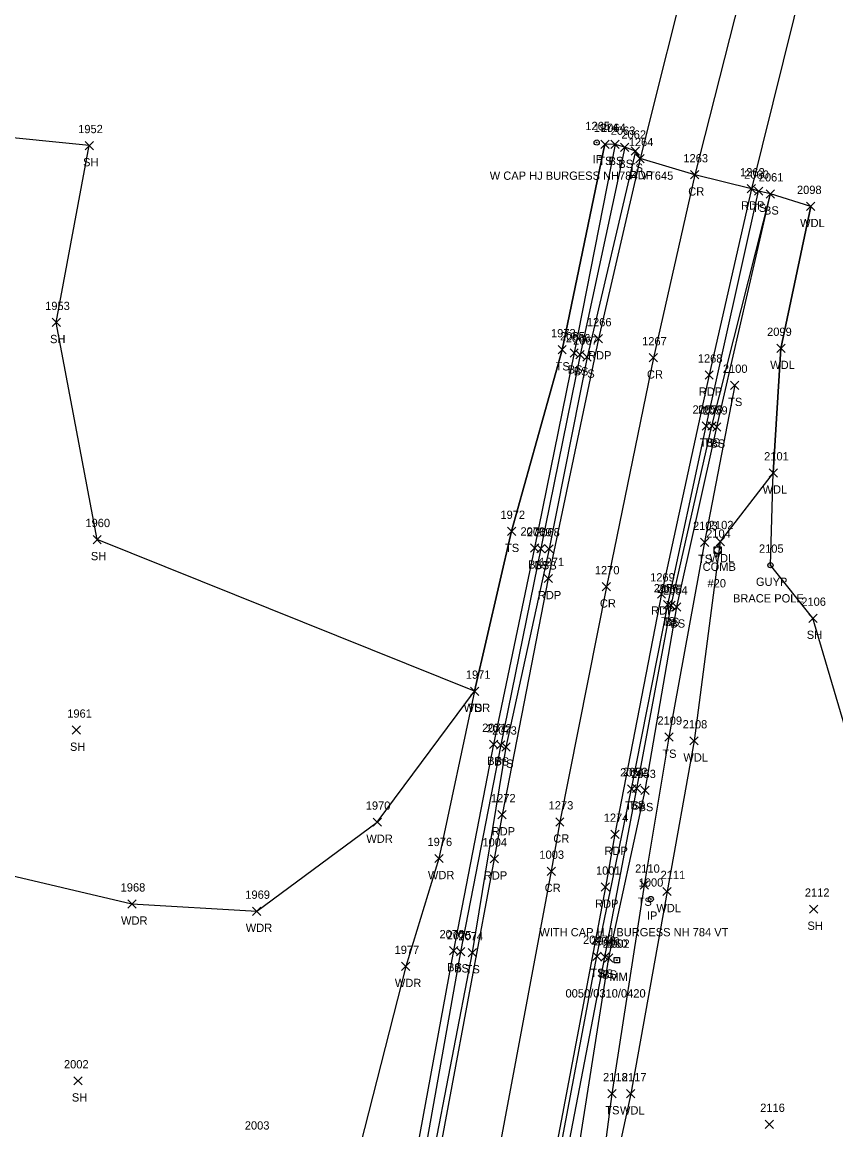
# Model space of a CAD drawing. Extents: x 1754529 to 1755810, y 621660 to 624656.
# Drawn here: x 1755421.2 to 1755617.5, y 624067.2 to 624334.6 of the extents above; entities that cross this region are included whole.
import ezdxf

# ---------------------------------------------------------------- set-up
doc = ezdxf.new("R2010")
doc.units = 0
for name, color, linetype in [('L_A', 7, 'Continuous'), ('L_I', 7, 'Continuous'), ('L_TIC', 7, 'Continuous'), ('LAWA', 7, 'Continuous'), ('LELB', 7, 'Continuous'), ('Level 14', 7, 'Continuous'), ('LSOGP', 7, 'Continuous'), ('M_A', 7, 'Continuous'), ('M_C', 7, 'Continuous'), ('M_I', 7, 'Continuous'), ('MPIR', 7, 'Continuous'), ('P_A', 7, 'Continuous'), ('P_I', 7, 'Continuous'), ('PET', 7, 'Continuous'), ('PRC', 7, 'Continuous'), ('S_A', 7, 'Continuous'), ('S_C', 7, 'Continuous'), ('S_I', 7, 'Continuous'), ('SRM', 7, 'Continuous'), ('U_A', 7, 'Continuous'), ('U_C', 7, 'Continuous'), ('U_I', 7, 'Continuous'), ('UP', 7, 'Continuous'), ('UPGW', 7, 'Continuous')]:
    doc.layers.add(name, color=color, linetype=linetype)

msp = doc.modelspace()

# ---------------------------------------------------------------- linework, layer by layer
at = {"layer": 'L_TIC'}
for points in [[(1755436.36, 624303.76), (1755438.36, 624305.76)], [(1755438.36, 624303.76), (1755436.36, 624305.76)], [(1755560.77, 624304.07), (1755562.77, 624306.07)], [(1755562.77, 624304.07), (1755560.77, 624306.07)], [(1755563.22, 624304.05), (1755565.22, 624306.05)], [(1755565.22, 624304.05), (1755563.22, 624306.05)], [(1755565.56, 624303.36), (1755567.56, 624305.36)], [(1755567.56, 624303.36), (1755565.56, 624305.36)], [(1755568.13, 624302.44), (1755570.13, 624304.44)], [(1755570.13, 624302.44), (1755568.13, 624304.44)], [(1755597.86, 624292.76), (1755599.86, 624294.76)], [(1755599.86, 624292.76), (1755597.86, 624294.76)], [(1755600.72, 624292.11), (1755602.72, 624294.11)], [(1755602.72, 624292.11), (1755600.72, 624294.11)], [(1755600.72, 624292.11), (1755602.72, 624294.11)], [(1755602.72, 624292.11), (1755600.72, 624294.11)], [(1755610.46, 624289.08), (1755612.46, 624291.08)], [(1755612.46, 624289.08), (1755610.46, 624291.08)], [(1755428.39, 624261.07), (1755430.39, 624263.07)], [(1755430.39, 624261.07), (1755428.39, 624263.07)], [(1755550.47, 624254.48), (1755552.47, 624256.48)], [(1755552.47, 624254.48), (1755550.47, 624256.48)], [(1755603.25, 624254.82), (1755605.25, 624256.82)], [(1755605.25, 624254.82), (1755603.25, 624256.82)], [(1755553.36, 624253.73), (1755555.36, 624255.73)], [(1755555.36, 624253.73), (1755553.36, 624255.73)], [(1755554.78, 624253.28), (1755556.78, 624255.28)], [(1755556.78, 624253.28), (1755554.78, 624255.28)], [(1755556.49, 624252.71), (1755558.49, 624254.71)], [(1755558.49, 624252.71), (1755556.49, 624254.71)], [(1755592.11, 624245.9), (1755594.11, 624247.9)], [(1755594.11, 624245.9), (1755592.11, 624247.9)], [(1755585.25, 624236.06), (1755587.25, 624238.06)], [(1755587.25, 624236.06), (1755585.25, 624238.06)], [(1755586.59, 624236.08), (1755588.59, 624238.08)], [(1755588.59, 624236.08), (1755586.59, 624238.08)], [(1755587.79, 624235.83), (1755589.79, 624237.83)], [(1755589.79, 624235.83), (1755587.79, 624237.83)], [(1755601.4, 624224.76), (1755603.4, 624226.76)], [(1755603.4, 624224.76), (1755601.4, 624226.76)], [(1755538.26, 624210.65), (1755540.26, 624212.65)], [(1755540.26, 624210.65), (1755538.26, 624212.65)], [(1755438.25, 624208.67), (1755440.25, 624210.67)], [(1755440.25, 624208.67), (1755438.25, 624210.67)], [(1755543.82, 624206.63), (1755545.82, 624208.63)], [(1755545.82, 624206.63), (1755543.82, 624208.63)], [(1755545.32, 624206.47), (1755547.32, 624208.47)], [(1755547.32, 624206.47), (1755545.32, 624208.47)], [(1755547.32, 624206.42), (1755549.32, 624208.42)], [(1755549.32, 624206.42), (1755547.32, 624208.42)], [(1755584.82, 624208), (1755586.82, 624210)], [(1755586.82, 624208), (1755584.82, 624210)], [(1755588.62, 624208.18), (1755590.62, 624210.18)], [(1755590.62, 624208.18), (1755588.62, 624210.18)], [(1755575.95, 624192.92), (1755577.95, 624194.92)], [(1755577.95, 624192.92), (1755575.95, 624194.92)], [(1755576.75, 624192.77), (1755578.75, 624194.77)], [(1755578.75, 624192.77), (1755576.75, 624194.77)], [(1755578.12, 624192.4), (1755580.12, 624194.4)], [(1755580.12, 624192.4), (1755578.12, 624194.4)], [(1755610.99, 624189.67), (1755612.99, 624191.67)], [(1755612.99, 624189.67), (1755610.99, 624191.67)], [(1755529.35, 624172.06), (1755531.35, 624174.06)], [(1755531.35, 624172.06), (1755529.35, 624174.06)], [(1755529.35, 624172.06), (1755531.35, 624174.06)], [(1755531.35, 624172.06), (1755529.35, 624174.06)], [(1755433.2, 624162.66), (1755435.2, 624164.66)], [(1755435.2, 624162.66), (1755433.2, 624164.66)], [(1755576.23, 624160.97), (1755578.23, 624162.97)], [(1755578.23, 624160.97), (1755576.23, 624162.97)], [(1755533.93, 624159.24), (1755535.93, 624161.24)], [(1755535.93, 624159.24), (1755533.93, 624161.24)], [(1755535.63, 624159.1), (1755537.63, 624161.1)], [(1755537.63, 624159.1), (1755535.63, 624161.1)], [(1755536.91, 624158.58), (1755538.91, 624160.58)], [(1755538.91, 624158.58), (1755536.91, 624160.58)], [(1755582.3, 624160.08), (1755584.3, 624162.08)], [(1755584.3, 624160.08), (1755582.3, 624162.08)], [(1755567.22, 624148.47), (1755569.22, 624150.47)], [(1755569.22, 624148.47), (1755567.22, 624150.47)], [(1755568.47, 624148.58), (1755570.47, 624150.58)], [(1755570.47, 624148.58), (1755568.47, 624150.58)], [(1755570.46, 624148.1), (1755572.46, 624150.1)], [(1755572.46, 624148.1), (1755570.46, 624150.1)], [(1755505.85, 624140.45), (1755507.85, 624142.45)], [(1755507.85, 624140.45), (1755505.85, 624142.45)], [(1755520.71, 624131.68), (1755522.71, 624133.68)], [(1755522.71, 624131.68), (1755520.71, 624133.68)], [(1755570.27, 624125.25), (1755572.27, 624127.25)], [(1755572.27, 624125.25), (1755570.27, 624127.25)], [(1755575.77, 624123.71), (1755577.77, 624125.71)], [(1755577.77, 624123.71), (1755575.77, 624125.71)], [(1755446.66, 624120.7), (1755448.66, 624122.7)], [(1755448.66, 624120.7), (1755446.66, 624122.7)], [(1755476.75, 624118.95), (1755478.75, 624120.95)], [(1755478.75, 624118.95), (1755476.75, 624120.95)], [(1755611.16, 624119.45), (1755613.16, 624121.45)], [(1755613.16, 624119.45), (1755611.16, 624121.45)], [(1755524.26, 624109.43), (1755526.26, 624111.43)], [(1755526.26, 624109.43), (1755524.26, 624111.43)], [(1755525.96, 624109.16), (1755527.96, 624111.16)], [(1755527.96, 624109.16), (1755525.96, 624111.16)], [(1755528.76, 624108.95), (1755530.76, 624110.95)], [(1755530.76, 624108.95), (1755528.76, 624110.95)], [(1755558.84, 624108.07), (1755560.84, 624110.07)], [(1755560.84, 624108.07), (1755558.84, 624110.07)], [(1755560.79, 624107.88), (1755562.79, 624109.88)], [(1755562.79, 624107.88), (1755560.79, 624109.88)], [(1755561.72, 624107.68), (1755563.72, 624109.68)], [(1755563.72, 624107.68), (1755561.72, 624109.68)], [(1755512.72, 624105.64), (1755514.72, 624107.64)], [(1755514.72, 624105.64), (1755512.72, 624107.64)], [(1755433.66, 624078.01), (1755435.66, 624080.01)], [(1755435.66, 624078.01), (1755433.66, 624080.01)], [(1755562.46, 624074.91), (1755564.46, 624076.91)], [(1755564.46, 624074.91), (1755562.46, 624076.91)], [(1755567, 624074.88), (1755569, 624076.88)], [(1755569, 624074.88), (1755567, 624076.88)], [(1755600.43, 624067.51), (1755602.43, 624069.51)], [(1755602.43, 624067.51), (1755600.43, 624069.51)]]:
    msp.add_lwpolyline(points, dxfattribs=at)
at = {"layer": 'LAWA'}
for points in [[(1755302.36, 624324.44), (1755304.56, 624259.61), (1755306.26, 624221.06), (1755317.77, 624175.11), (1755335.71, 624145.2), (1755381.51, 624131.11), (1755414.09, 624129.63), (1755447.66, 624121.7), (1755477.75, 624119.95), (1755506.85, 624141.45), (1755530.35, 624173.06), (1755521.71, 624132.68), (1755513.72, 624106.64), (1755499.73, 624051.71), (1755491.49, 624010.7), (1755483.31, 623982.28), (1755477.84, 623954.98), (1755471.72, 623930.68), (1755463.31, 623898.52), (1755457.13, 623867.77), (1755453.48, 623847.93), (1755451.28, 623827.38), (1755449.92, 623802.26), (1755447.47, 623775.96)], [(1755611.46, 624290.08), (1755604.25, 624255.82), (1755602.4, 624225.76), (1755589.62, 624209.18), (1755583.3, 624161.08), (1755576.77, 624124.71), (1755568, 624075.88), (1755556.51, 624023.02), (1755550.67, 623972.84), (1755545.94, 623933.51), (1755542.23, 623896.35), (1755539.41, 623871.88), (1755536.68, 623848.06)]]:
    msp.add_lwpolyline(points, dxfattribs=at)
at = {"layer": 'LELB'}
for points in [[(1755564.22, 624305.05), (1755554.36, 624254.73), (1755544.82, 624207.63), (1755534.93, 624160.24), (1755525.26, 624110.43), (1755515.97, 624060.22), (1755506.84, 624008.91), (1755495.69, 623948.15), (1755487.4, 623901.21), (1755479.14, 623855.5), (1755472.16, 623816.92), (1755467.3, 623794.24)], [(1755530.35, 624173.06), (1755539.26, 624211.65), (1755551.47, 624255.48), (1755561.77, 624305.07)], [(1755566.56, 624304.36), (1755555.78, 624254.28), (1755546.32, 624207.47), (1755536.63, 624160.1), (1755526.96, 624110.16), (1755517.91, 624059.57), (1755508.44, 624008.83), (1755498, 623948.21), (1755488.64, 623901.37), (1755480.93, 623855.25), (1755473.47, 623816.7), (1755469.09, 623793.73)], [(1755569.13, 624303.44), (1755557.49, 624253.71), (1755548.32, 624207.42), (1755537.91, 624159.58), (1755529.76, 624109.95), (1755519.9, 624059.12), (1755510.42, 624008.64), (1755499.16, 623947.88), (1755490.5, 623900.71), (1755482.67, 623854.46), (1755475.56, 623816.58), (1755471.08, 623793.12)], [(1755503.59, 623800.12), (1755513.5, 623853.71), (1755523.35, 623909.32), (1755532.32, 623959.16), (1755541.82, 624011.12), (1755549.93, 624056.68), (1755559.84, 624109.07), (1755568.22, 624149.47), (1755576.95, 624193.92), (1755586.25, 624237.06), (1755598.86, 624293.76)], [(1755505.03, 623799.81), (1755514.71, 623853.68), (1755525.28, 623909.17), (1755534.08, 623958.86), (1755543.64, 624010.85), (1755551.62, 624056.17), (1755561.79, 624108.88), (1755569.47, 624149.58), (1755577.75, 624193.77), (1755587.59, 624237.08), (1755601.72, 624293.11)], [(1755506.63, 623799.61), (1755516.45, 623853.4), (1755526.55, 623908.94), (1755535.77, 623958.34), (1755544.53, 624010.84), (1755554.4, 624055.49), (1755562.72, 624108.68), (1755571.46, 624149.1), (1755579.12, 624193.4), (1755588.79, 624236.83), (1755601.72, 624293.11)], [(1755593.11, 624246.9), (1755585.82, 624209), (1755577.23, 624161.97), (1755571.27, 624126.25), (1755563.46, 624075.91), (1755556.51, 624023.02)]]:
    msp.add_lwpolyline(points, dxfattribs=at)
at = {"layer": 'Level 14'}
for points in [[(1755569.27, 624300.63), (1755571.27, 624302.63)], [(1755571.27, 624300.63), (1755569.27, 624302.63)], [(1755582.45, 624296.71), (1755584.45, 624298.71)], [(1755584.45, 624296.71), (1755582.45, 624298.71)], [(1755596.12, 624293.33), (1755598.12, 624295.33)], [(1755598.12, 624293.33), (1755596.12, 624295.33)], [(1755559.22, 624257.14), (1755561.22, 624259.14)], [(1755561.22, 624257.14), (1755559.22, 624259.14)], [(1755572.49, 624252.54), (1755574.49, 624254.54)], [(1755574.49, 624252.54), (1755572.49, 624254.54)], [(1755585.94, 624248.39), (1755587.94, 624250.39)], [(1755587.94, 624248.39), (1755585.94, 624250.39)], [(1755547.1, 624199.26), (1755549.1, 624201.26)], [(1755549.1, 624199.26), (1755547.1, 624201.26)], [(1755561.13, 624197.27), (1755563.13, 624199.27)], [(1755563.13, 624197.27), (1755561.13, 624199.27)], [(1755574.43, 624195.55), (1755576.43, 624197.55)], [(1755576.43, 624195.55), (1755574.43, 624197.55)], [(1755535.97, 624142.24), (1755537.97, 624144.24)], [(1755537.97, 624142.24), (1755535.97, 624144.24)], [(1755549.9, 624140.51), (1755551.9, 624142.51)], [(1755551.9, 624140.51), (1755549.9, 624142.51)], [(1755563.19, 624137.53), (1755565.19, 624139.53)], [(1755565.19, 624137.53), (1755563.19, 624139.53)], [(1755534.07, 624131.59), (1755536.07, 624133.59)], [(1755536.07, 624131.59), (1755534.07, 624133.59)], [(1755547.82, 624128.6), (1755549.82, 624130.6)], [(1755549.82, 624128.6), (1755547.82, 624130.6)], [(1755560.91, 624124.77), (1755562.91, 624126.77)], [(1755562.91, 624124.77), (1755560.91, 624126.77)]]:
    msp.add_lwpolyline(points, dxfattribs=at)
at = {"layer": 'LSOGP'}
msp.add_lwpolyline([(1755642.06, 624060.86), (1755626.78, 624116.47), (1755621.8, 624157.48), (1755611.99, 624190.67), (1755601.72, 624203.48), (1755602.4, 624225.76), (1755604.25, 624255.82), (1755611.46, 624290.08), (1755601.72, 624293.11), (1755598.86, 624293.76), (1755597.12, 624294.33), (1755583.45, 624297.71), (1755570.27, 624301.63), (1755569.13, 624303.44), (1755566.56, 624304.36), (1755564.22, 624305.05), (1755561.77, 624305.07), (1755551.47, 624255.48), (1755539.26, 624211.65), (1755530.35, 624173.06), (1755439.25, 624209.67), (1755429.39, 624262.07), (1755437.36, 624304.76), (1755388.37, 624309.67)], dxfattribs=at)
at = {"layer": 'MPIR'}
for centre, radius in [((1755559.8, 624305.5), 0.625), ((1755559.8, 624305.5), 0.0833), ((1755572.86, 624122.89), 0.625), ((1755572.86, 624122.89), 0.0833)]:
    msp.add_circle(centre, radius, dxfattribs=at)
at = {"layer": 'PET'}
for points in [[(1755583.24, 624353.4), (1755570.27, 624301.63), (1755560.22, 624258.14), (1755548.1, 624200.26), (1755536.97, 624143.24)], [(1755609.98, 624345.99), (1755597.12, 624294.33), (1755586.94, 624249.39), (1755575.43, 624196.55), (1755564.19, 624138.53)], [(1755536.97, 624143.24), (1755535.07, 624132.59)], [(1755564.19, 624138.53), (1755561.91, 624125.77)], [(1755535.07, 624132.59), (1755507.27, 623983.72), (1755476.9, 623815.46), (1755460.3, 623719.87), (1755437.79, 623591.8), (1755421.36, 623504.45), (1755418.26, 623495.73), (1755404.2, 623424.5), (1755397.43, 623386.49), (1755390.98, 623344.71), (1755391.72, 623340.77), (1755385.02, 623296.56), (1755379.33, 623252.08), (1755376.53, 623216.25), (1755375.95, 623174.43), (1755377.19, 623132.58)], [(1755561.91, 624125.77), (1755533.66, 623976.91), (1755504.04, 623811.48), (1755486.8, 623713.65), (1755464.22, 623587.1), (1755446.31, 623490.47), (1755433.28, 623420.6), (1755425.75, 623380.35), (1755417.64, 623332.29), (1755411.38, 623292.51), (1755405.94, 623251.45), (1755403.49, 623215.07), (1755403.14, 623175.05), (1755404.1, 623131.29)]]:
    msp.add_lwpolyline(points, dxfattribs=at)
at = {"layer": 'PRC'}
for points in [[(1755596.62, 624349.32), (1755583.45, 624297.71), (1755573.49, 624253.54), (1755562.13, 624198.27), (1755550.9, 624141.51)], [(1755550.9, 624141.51), (1755548.82, 624129.6)], [(1755548.82, 624129.6), (1755520.89, 623980.45), (1755490.93, 623813.93), (1755473.47, 623716.78), (1755450.77, 623588.43), (1755432.8, 623492.49), (1755420.05, 623422.21), (1755412.93, 623383.28), (1755404.64, 623333.82), (1755398.35, 623294.75), (1755393.11, 623251.83), (1755390.3, 623215.98), (1755389.28, 623175.01), (1755390.29, 623132.74)]]:
    msp.add_lwpolyline(points, dxfattribs=at)
at = {"layer": 'SRM'}
for points in [[(1755564.02, 624108.75), (1755565.27, 624108.75), (1755565.27, 624107.5), (1755564.02, 624107.5)], [(1755564.04, 624108.76), (1755565.29, 624108.76), (1755565.29, 624107.51), (1755564.04, 624107.51)]]:
    msp.add_lwpolyline(points, close=True, dxfattribs=at)
for centre in [(1755564.65, 624108.12), (1755564.67, 624108.13)]:
    msp.add_circle(centre, 0.0833, dxfattribs=at)
at = {"layer": 'UP'}
for p, q in [((1755589.23, 624208.78), (1755588.98, 624207.94)), ((1755588.14, 624206.28), (1755588.14, 624207.94)), ((1755588.14, 624207.94), (1755589.81, 624207.94)), ((1755589.81, 624206.28), (1755588.14, 624206.28)), ((1755588.73, 624205.44), (1755588.98, 624206.28)), ((1755588.98, 624207.11), (1755588.98, 624207.11)), ((1755589.81, 624207.94), (1755589.81, 624206.28))]:
    msp.add_line(p, q, dxfattribs=at)
msp.add_circle((1755588.98, 624207.11), 0.833, dxfattribs=at)
at = {"layer": 'UPGW'}
for radius in [0.625, 0.0833]:
    msp.add_circle((1755601.72, 624203.48), radius, dxfattribs=at)

# ---------------------------------------------------------------- texts
at = {"layer": 'L_A'}
for s, p in [('SH', (1755435.85, 624299.76)), ('TS', (1755560.18, 624300.07)), ('BS', (1755562.66, 624300.05)), ('BS', (1755565.01, 624299.36)), ('TS', (1755567.54, 624298.44)), ('TS', (1755597.27, 624288.76)), ('BS', (1755600.16, 624288.11)), ('BS', (1755600.16, 624288.11)), ('WDL', (1755608.88, 624285.08)), ('SH', (1755427.88, 624257.07)), ('TS', (1755549.88, 624250.48)), ('BS', (1755552.8, 624249.73)), ('BS', (1755554.23, 624249.28)), ('WDL', (1755601.67, 624250.82)), ('TS', (1755555.9, 624248.71)), ('TS', (1755591.52, 624241.9)), ('TS', (1755584.66, 624232.06)), ('BS', (1755586.03, 624232.08)), ('BS', (1755587.23, 624231.83)), ('WDL', (1755599.82, 624220.76)), ('TS', (1755537.67, 624206.65)), ('SH', (1755437.74, 624204.67)), ('TS', (1755584.23, 624204)), ('WDL', (1755587.03, 624204.18)), ('BS', (1755543.26, 624202.63)), ('BS', (1755544.76, 624202.47)), ('TS', (1755546.73, 624202.42)), ('TS', (1755575.36, 624188.92)), ('BS', (1755576.19, 624188.77)), ('BS', (1755577.57, 624188.4)), ('SH', (1755610.48, 624185.67)), ('WDR', (1755527.71, 624168.06)), ('TS', (1755528.76, 624168.06)), ('SH', (1755432.69, 624158.66)), ('TS', (1755575.64, 624156.97)), ('WDL', (1755580.71, 624156.08)), ('BS', (1755533.37, 624155.24)), ('BS', (1755535.07, 624155.1)), ('TS', (1755536.31, 624154.58)), ('TS', (1755566.63, 624144.47)), ('BS', (1755567.91, 624144.58)), ('BS', (1755569.9, 624144.1)), ('WDR', (1755504.21, 624136.45)), ('WDR', (1755519.07, 624127.68)), ('TS', (1755569.68, 624121.25)), ('WDL', (1755574.19, 624119.71)), ('WDR', (1755445.02, 624116.7)), ('SH', (1755610.65, 624115.45)), ('WDR', (1755475.11, 624114.95)), ('BS', (1755523.7, 624105.43)), ('BS', (1755525.4, 624105.16)), ('TS', (1755528.17, 624104.95)), ('TS', (1755558.25, 624104.07)), ('BS', (1755560.23, 624103.88)), ('BS', (1755561.16, 624103.68)), ('WDR', (1755511.09, 624101.64)), ('SH', (1755433.15, 624074.01)), ('TS', (1755561.87, 624070.91)), ('WDL', (1755565.41, 624070.88))]:
    msp.add_text(s, height=2, dxfattribs=at).set_placement(p)
at = {"layer": 'L_I'}
for s, p in [('1952', (1755434.67, 624307.76)), ('1974', (1755559.08, 624308.07)), ('2064', (1755560.83, 624308.05)), ('2063', (1755563.18, 624307.36)), ('2062', (1755565.75, 624306.44)), ('2060', (1755595.39, 624296.76)), ('2061', (1755598.9, 624296.11)), ('2061', (1755598.9, 624296.11)), ('2098', (1755608.12, 624293.08)), ('1953', (1755426.7, 624265.07)), ('1973', (1755548.77, 624258.48)), ('2065', (1755550.97, 624257.73)), ('2066', (1755552.34, 624257.28)), ('2099', (1755600.91, 624258.82)), ('2067', (1755554.11, 624256.71)), ('2100', (1755590.25, 624249.9)), ('2057', (1755582.91, 624240.06)), ('2058', (1755584.25, 624240.08)), ('2059', (1755585.44, 624239.83)), ('2101', (1755600.2, 624228.76)), ('1972', (1755536.56, 624214.65)), ('1960', (1755436.42, 624212.67)), ('2103', (1755583.04, 624212)), ('2102', (1755586.85, 624212.18)), ('2070', (1755541.4, 624210.63)), ('2069', (1755542.93, 624210.47)), ('2068', (1755544.94, 624210.42)), ('2056', (1755573.56, 624196.92)), ('2055', (1755574.41, 624196.77)), ('2054', (1755575.79, 624196.4)), ('2106', (1755609.17, 624193.67)), ('1971', (1755528.22, 624176.06)), ('1971', (1755528.22, 624176.06)), ('1961', (1755432.03, 624166.66)), ('2109', (1755574.45, 624164.97)), ('2108', (1755580.53, 624164.08)), ('2071', (1755532.16, 624163.24)), ('2072', (1755533.29, 624163.1)), ('2073', (1755534.57, 624162.58)), ('2051', (1755565.45, 624152.47)), ('2052', (1755566.13, 624152.58)), ('2053', (1755568.12, 624152.1)), ('1970', (1755504.07, 624144.45)), ('1976', (1755518.96, 624135.68)), ('2110', (1755569.06, 624129.25)), ('2111', (1755575.21, 624127.71)), ('1968', (1755444.92, 624124.7)), ('2112', (1755610.03, 624123.45)), ('1969', (1755475, 624122.95)), ('2076', (1755521.87, 624113.43)), ('2075', (1755523.62, 624113.16)), ('2074', (1755526.42, 624112.95)), ('2047', (1755556.5, 624112.07)), ('2048', (1755558.45, 624111.88)), ('2049', (1755559.38, 624111.68)), ('1977', (1755511.03, 624109.64)), ('2002', (1755431.24, 624082.01)), ('2118', (1755561.33, 624078.91)), ('2117', (1755565.87, 624078.88)), ('2116', (1755599.25, 624071.51)), ('2003', (1755474.88, 624067.24))]:
    msp.add_text(s, height=2, dxfattribs=at).set_placement(p)
at = {"layer": 'M_A'}
for p in [(1755558.84, 624300.5), (1755571.91, 624117.89)]:
    msp.add_text('IP', height=2, dxfattribs=at).set_placement(p)
at = {"layer": 'M_C'}
for s, p in [('W CAP HJ BURGESS NH784 VT645', (1755533.99, 624296.5)), ('WITH CAP H J BURGESS NH 784 VT', (1755545.96, 624113.89))]:
    msp.add_text(s, height=2, dxfattribs=at).set_placement(p)
at = {"layer": 'M_I'}
for s, p in [('1265', (1755557.06, 624308.5)), ('1000', (1755569.92, 624125.89))]:
    msp.add_text(s, height=2, dxfattribs=at).set_placement(p)
at = {"layer": 'P_A'}
for s, p in [('RDP', (1755567.76, 624296.63)), ('CR', (1755581.89, 624292.71)), ('RDP', (1755594.61, 624289.33)), ('RDP', (1755557.71, 624253.14)), ('CR', (1755571.93, 624248.54)), ('RDP', (1755584.43, 624244.39)), ('RDP', (1755545.59, 624195.26)), ('CR', (1755560.57, 624193.27)), ('RDP', (1755572.92, 624191.55)), ('RDP', (1755534.46, 624138.24)), ('CR', (1755549.33, 624136.51)), ('RDP', (1755561.68, 624133.53)), ('RDP', (1755532.56, 624127.59)), ('CR', (1755547.25, 624124.6)), ('RDP', (1755559.4, 624120.77))]:
    msp.add_text(s, height=2, dxfattribs=at).set_placement(p)
at = {"layer": 'P_I'}
for s, p in [('1264', (1755567.53, 624304.63)), ('1263', (1755580.71, 624300.71)), ('1262', (1755594.38, 624297.33)), ('1266', (1755557.43, 624261.14)), ('1267', (1755570.75, 624256.54)), ('1268', (1755584.2, 624252.39)), ('1271', (1755545.97, 624203.26)), ('1270', (1755559.35, 624201.27)), ('1269', (1755572.69, 624199.55)), ('1272', (1755534.28, 624146.24)), ('1273', (1755548.2, 624144.51)), ('1274', (1755561.5, 624141.53)), ('1004', (1755532.22, 624135.59)), ('1003', (1755545.97, 624132.6)), ('1001', (1755559.63, 624128.77))]:
    msp.add_text(s, height=2, dxfattribs=at).set_placement(p)
at = {"layer": 'S_A'}
for p in [(1755562.84, 624103.12), (1755562.86, 624103.13)]:
    msp.add_text('MM', height=2, dxfattribs=at).set_placement(p)
at = {"layer": 'S_C'}
for p in [(1755552.26, 624099.12), (1755552.28, 624099.13)]:
    msp.add_text('0050/0310/0420', height=2, dxfattribs=at).set_placement(p)
at = {"layer": 'S_I'}
for s, p in [('2050', (1755561.24, 624111.13)), ('1002', (1755561.8, 624111.12))]:
    msp.add_text(s, height=2, dxfattribs=at).set_placement(p)
at = {"layer": 'U_A'}
for s, p in [('COMB', (1755585.36, 624202.11)), ('GUYP', (1755598.23, 624198.48))]:
    msp.add_text(s, height=2, dxfattribs=at).set_placement(p)
at = {"layer": 'U_C'}
for s, p in [('#20', (1755586.53, 624198.11)), ('BRACE POLE', (1755592.68, 624194.48))]:
    msp.add_text(s, height=2, dxfattribs=at).set_placement(p)
at = {"layer": 'U_I'}
for s, p in [('2104', (1755586.21, 624210.11)), ('2105', (1755598.95, 624206.48))]:
    msp.add_text(s, height=2, dxfattribs=at).set_placement(p)

doc.saveas('drawing.dxf')
